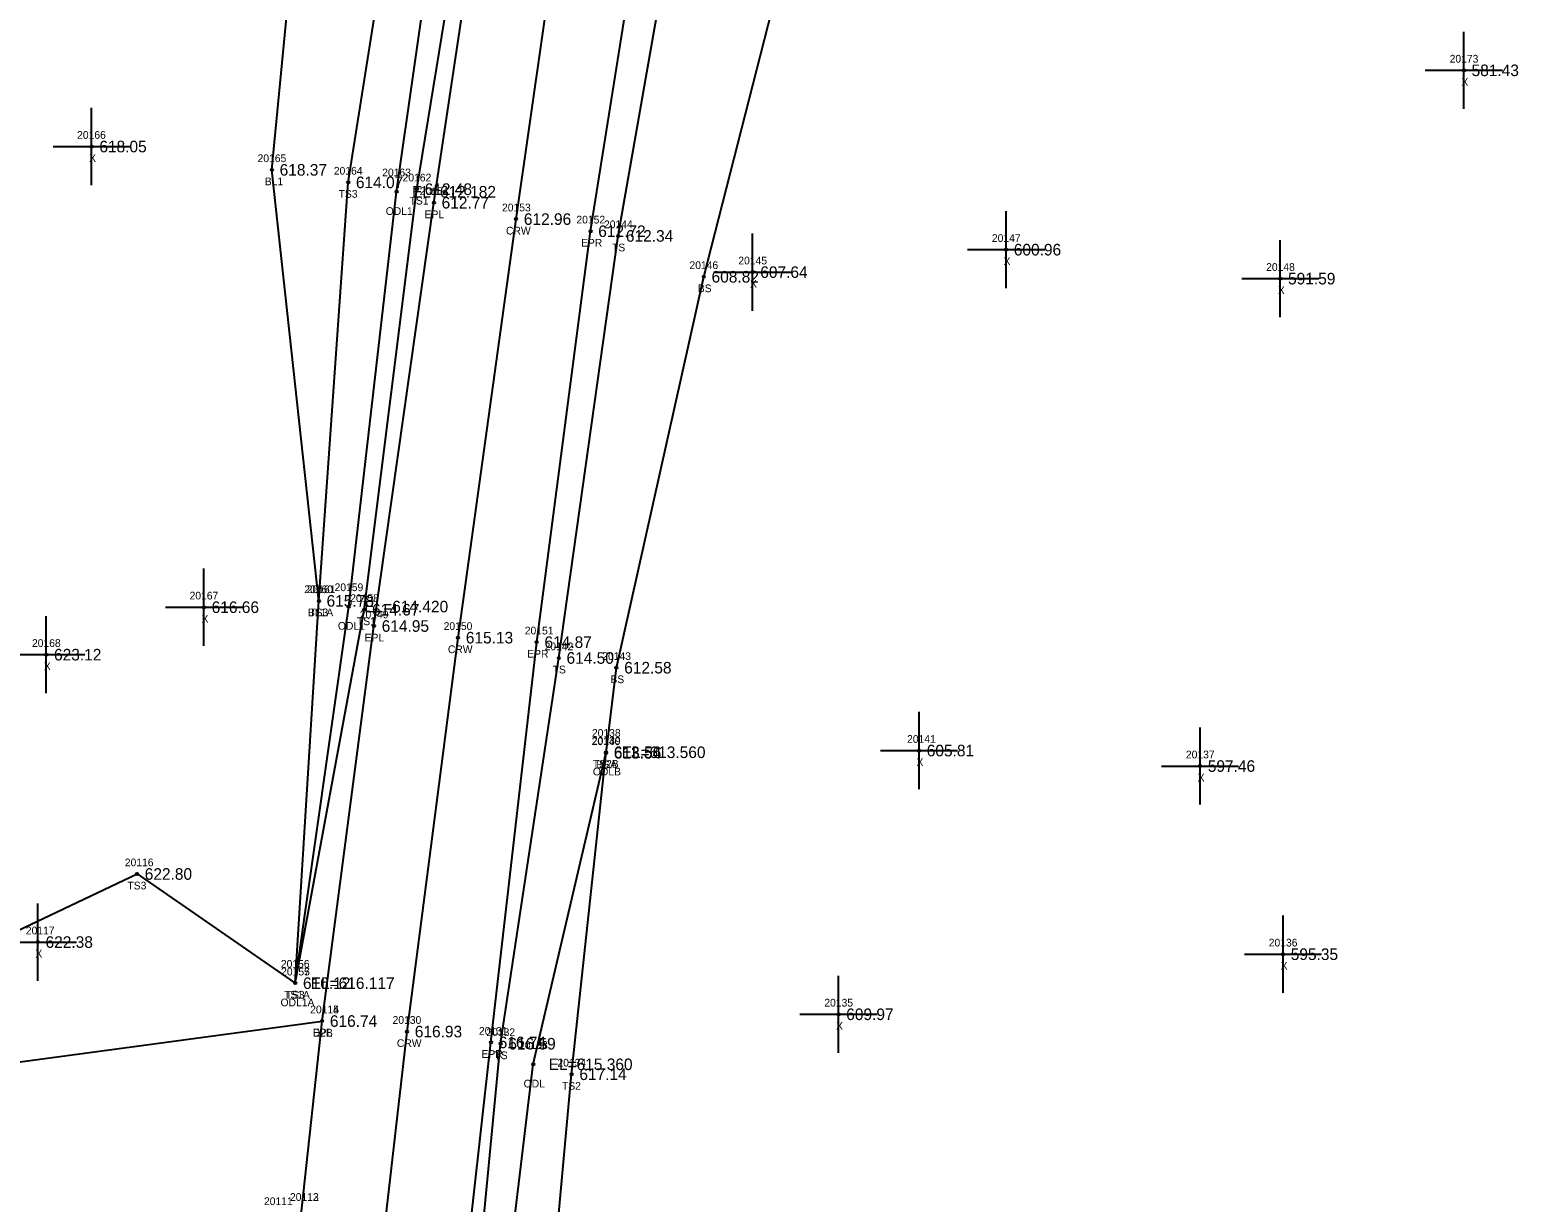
# Model space of a CAD drawing. Extents: x 1695443 to 1696344, y 1087542 to 1090645.
# Drawn here: x 1695882.4 to 1696075.2, y 1088055.6 to 1088207.5 of the extents above; entities that cross this region are included whole.
import ezdxf

# ---------------------------------------------------------------- set-up
doc = ezdxf.new("R2010")
doc.units = 0
for name, color, linetype in [('RD_DTM_BkLn1', 7, 'Continuous'), ('RD_DTM_BkLn2', 7, 'Continuous'), ('RD_DTM_BkLn_txCode', 7, 'Continuous'), ('RD_EX_Driveway', 7, 'Continuous'), ('RD_EX_Driveway_txCode', 7, 'Continuous'), ('RD_EX_H2O', 7, 'Continuous'), ('RD_EX_H2O_txCode', 7, 'Continuous'), ('RD_EX_Misc', 7, 'Continuous'), ('RD_EX_Misc_txCode', 7, 'Continuous'), ('RD_EX_Road', 7, 'Continuous'), ('RD_EX_Road_txCode', 7, 'Continuous'), ('RD_EX_TX_Driveway_ELEV', 7, 'Continuous'), ('RD_EX_TX_H2O_ELEV', 7, 'Continuous'), ('RD_EX_TX_Misc_ELEV', 7, 'Continuous'), ('RD_EX_TX_Road_ELEV', 7, 'Continuous'), ('RD_HC_Survey_ELEV', 7, 'Continuous'), ('RD_HC_Survey_txCode', 7, 'Continuous'), ('RD_SMD_Locator', 7, 'Continuous')]:
    doc.layers.add(name, color=color, linetype=linetype)

msp = doc.modelspace()

# ---------------------------------------------------------------- linework, layer by layer
at = {"layer": 'RD_DTM_BkLn1'}
for points in [[(1695869.23, 1087563.38), (1695882.71, 1087666.87), (1695895.39, 1087768.85), (1695908.05, 1087871.3), (1695919.71, 1087974.19), (1695925.35, 1088026.13), (1695931.27, 1088077.73), (1695937.88, 1088128.75), (1695945.4, 1088182.97), (1695952.48, 1088232.38), (1695961.74, 1088286.36), (1695971.36, 1088336.92), (1695982.91, 1088390.82), (1696009.16, 1088497.22), (1696035.45, 1088601.7), (1696045.5, 1088655.66), (1696049.03, 1088705.78), (1696045.47, 1088756.42), (1696033.82, 1088809.1), (1696016.78, 1088855.71), (1695990.89, 1088906.17), (1695964.41, 1088947.39), (1695931.21, 1088992.88)], [(1695919.84, 1088133.52), (1695913.76, 1088189.35), (1695918.21, 1088235.47), (1695922.76, 1088289.81), (1695929.86, 1088337.9), (1695944.4, 1088398.9), (1695974.86, 1088502.33), (1696013.19, 1088605.35)]]:
    msp.add_lwpolyline(points, dxfattribs=at)
at = {"layer": 'RD_DTM_BkLn2'}
for points in [[(1695957.06, 1088113.83), (1695958.4, 1088124.86), (1695969.72, 1088175.5), (1695984.45, 1088233.12), (1695986.34, 1088280.33), (1695995.02, 1088332.7), (1696009.2, 1088386.54), (1696038.3, 1088489.24), (1696061.78, 1088594.39), (1696062.98, 1088655.37), (1696069.05, 1088704.28), (1696065.26, 1088759.68), (1696052.53, 1088814.08), (1696046.96, 1088869.93), (1696016.66, 1088919.05), (1695997.75, 1088967.45), (1695944.59, 1089014.67), (1695937.23, 1089009.08)], [(1695916.78, 1088084), (1695925.73, 1088132.37), (1695932.55, 1088186.85), (1695940.12, 1088233.39), (1695949.48, 1088288.14), (1695959.7, 1088339.01), (1695971.73, 1088394.21), (1695997.36, 1088500.21), (1696023.08, 1088603.25), (1696032.92, 1088656.94), (1696036.1, 1088705.18), (1696032.76, 1088754.54), (1696021.34, 1088805.78), (1696004.42, 1088850.43), (1695979.2, 1088899.43), (1695947.85, 1088934.07), (1695935.29, 1088941.42), (1695930.1, 1088962.13), (1695923.44, 1088976.06), (1695917.46, 1088980.5), (1695920.03, 1088983.92)], [(1695811.33, 1088056.44), (1695848.8, 1088075.62), (1695896.28, 1088098.14), (1695916.78, 1088084), (1695919.84, 1088133.52), (1695923.64, 1088187.73), (1695930.8, 1088232.96), (1695939.58, 1088289.44), (1695949.3, 1088339.9), (1695960.86, 1088397.31), (1695988.69, 1088500.86), (1696013.19, 1088605.35), (1696020.87, 1088659.75), (1696023.4, 1088706.14), (1696018.3, 1088755.38), (1696009.58, 1088802.31), (1695993.24, 1088846.7), (1695969.88, 1088894.03), (1695962.8, 1088910.68)], [(1695882.6, 1087560.4), (1695895.55, 1087664.54), (1695908.06, 1087766.74), (1695920.67, 1087869.68), (1695933.47, 1087972.17), (1695938.06, 1088020.68), (1695943.39, 1088076.15), (1695950.93, 1088126.12), (1695958.62, 1088180.79), (1695967.59, 1088232.03), (1695975.32, 1088283.22), (1695985.14, 1088336.17), (1695996.59, 1088387.88), (1696023.18, 1088492.82), (1696049.23, 1088599.85), (1696058.32, 1088654.25)], [(1695882.6, 1087560.4), (1695883.79, 1087555.85), (1695890.5, 1087560.67), (1695906.06, 1087668.38), (1695920.19, 1087765.58), (1695932.4, 1087870.37), (1695944.02, 1087970.73), (1695947.56, 1088017.12), (1695952.59, 1088072.2), (1695957.06, 1088113.91)]]:
    msp.add_lwpolyline(points, dxfattribs=at)
at = {"layer": 'RD_EX_Driveway'}
msp.add_lwpolyline([(1695811.33, 1088056.44), (1695845.15, 1088068.97), (1695920.27, 1088079.09)], dxfattribs=at)
at = {"layer": 'RD_EX_H2O'}
for points in [[(1695916.78, 1088084), (1695923.72, 1088132.78), (1695929.91, 1088186.51), (1695936.75, 1088234.45), (1695946.8, 1088289.18), (1695957.47, 1088339.74), (1695969.14, 1088394.61), (1695994.85, 1088500.6), (1696021.07, 1088603.21), (1696031.1, 1088657.25), (1696033.92, 1088705.19), (1696029.81, 1088754.45), (1696018.23, 1088805.15), (1696001.4, 1088849.48), (1695973.58, 1088895.84), (1695962.8, 1088910.68)], [(1695884.7, 1087558.83), (1695897.39, 1087664.39), (1695910.4, 1087766.5), (1695924.17, 1087869.12), (1695936.94, 1087971.73), (1695941.17, 1088019.96), (1695947.61, 1088073.49), (1695957.06, 1088113.91)]]:
    msp.add_lwpolyline(points, dxfattribs=at)
at = {"layer": 'RD_EX_Misc'}
for p, q in [((1696068.19, 1088197.24), (1696068.19, 1088207.24)), ((1696063.19, 1088202.24), (1696073.19, 1088202.24)), ((1695890.4, 1088187.37), (1695890.4, 1088197.37)), ((1695885.4, 1088192.37), (1695895.4, 1088192.37)), ((1696008.88, 1088174.01), (1696008.88, 1088184.01)), ((1695976.03, 1088171.1), (1695976.03, 1088181.1)), ((1696044.41, 1088170.26), (1696044.41, 1088180.26)), ((1696003.88, 1088179.01), (1696013.88, 1088179.01)), ((1695971.03, 1088176.1), (1695981.03, 1088176.1)), ((1696039.41, 1088175.26), (1696049.41, 1088175.26)), ((1695904.95, 1088127.7), (1695904.95, 1088137.7)), ((1695884.53, 1088121.55), (1695884.53, 1088131.55)), ((1695899.95, 1088132.7), (1695909.95, 1088132.7)), ((1695879.53, 1088126.55), (1695889.53, 1088126.55)), ((1695997.6, 1088109.13), (1695997.6, 1088119.13)), ((1696034.01, 1088107.12), (1696034.01, 1088117.12)), ((1695992.6, 1088114.13), (1696002.6, 1088114.13)), ((1696029.01, 1088112.12), (1696039.01, 1088112.12)), ((1695883.43, 1088084.32), (1695883.43, 1088094.32)), ((1696044.76, 1088082.75), (1696044.76, 1088092.75)), ((1695878.43, 1088089.32), (1695888.43, 1088089.32)), ((1696039.76, 1088087.75), (1696049.76, 1088087.75)), ((1695987.17, 1088074.97), (1695987.17, 1088084.97)), ((1695982.17, 1088079.97), (1695992.17, 1088079.97))]:
    msp.add_line(p, q, dxfattribs=at)
at = {"layer": 'RD_EX_Road'}
for points in [[(1695879.87, 1087561.29), (1695893.33, 1087665.71), (1695905.96, 1087767.16), (1695918.66, 1087869.54), (1695930.87, 1087972.82), (1695936.26, 1088023.68), (1695942.14, 1088076.32), (1695948.07, 1088128.17), (1695955.04, 1088181.4), (1695962.88, 1088230.72), (1695971.68, 1088284.64), (1695982.02, 1088336.12), (1695993.28, 1088388.48), (1696018.75, 1088494.48), (1696045.23, 1088599.95), (1696055.72, 1088654.41), (1696060.15, 1088705.35), (1696055.83, 1088758.02), (1696044.01, 1088812.16), (1696026.4, 1088860.33), (1696000.41, 1088911.48), (1695972.46, 1088953.82), (1695939.48, 1088998.73), (1695931.21, 1088992.88)], [(1695858.19, 1087564.9), (1695871.71, 1087668.82), (1695884.5, 1087774.69), (1695887.48, 1087794.2), (1695897.57, 1087873.43), (1695908.92, 1087975.76), (1695914.49, 1088029.24), (1695917.65, 1088054.8), (1695920.27, 1088079.09), (1695926.98, 1088130.26), (1695934.75, 1088185.09), (1695942.15, 1088234.62), (1695951.36, 1088288.06), (1695961.48, 1088338.41), (1695972.86, 1088394.13), (1695998.53, 1088499.67), (1696024.81, 1088603.86), (1696034.83, 1088656.78)]]:
    msp.add_lwpolyline(points, dxfattribs=at)
at = {"layer": 'RD_SMD_Locator'}
for centre in [(1696068.19, 1088202.24), (1695890.4, 1088192.37), (1695913.76, 1088189.35), (1695923.64, 1088187.73), (1695929.91, 1088186.51), (1695932.55, 1088186.85), (1695934.75, 1088185.09), (1695945.4, 1088182.97), (1695955.04, 1088181.4), (1695958.62, 1088180.79), (1696008.88, 1088179.01), (1695969.72, 1088175.5), (1695976.03, 1088176.1), (1696044.41, 1088175.26), (1695919.84, 1088133.52), (1695919.84, 1088133.52), (1695904.95, 1088132.7), (1695923.72, 1088132.78), (1695925.73, 1088132.37), (1695926.98, 1088130.26), (1695937.88, 1088128.75), (1695948.07, 1088128.17), (1695884.53, 1088126.55), (1695950.93, 1088126.12), (1695958.4, 1088124.86), (1695957.06, 1088113.91), (1695957.06, 1088113.91), (1695957.06, 1088113.83), (1695997.6, 1088114.13), (1696034.01, 1088112.12), (1695896.28, 1088098.14), (1695883.43, 1088089.32), (1696044.76, 1088087.75), (1695916.78, 1088084), (1695916.78, 1088084), (1695916.78, 1088084), (1695920.27, 1088079.09), (1695920.27, 1088079.09), (1695987.17, 1088079.97), (1695931.27, 1088077.73), (1695942.14, 1088076.32), (1695943.39, 1088076.15), (1695947.61, 1088073.49), (1695952.59, 1088072.2)]:
    msp.add_circle(centre, 0.15, dxfattribs=at)

# ---------------------------------------------------------------- texts
at = {"layer": 'RD_DTM_BkLn_txCode'}
for s, p in [('20165', (1695911.9, 1088190.35)), ('20164', (1695921.78, 1088188.73)), ('BL1', (1695912.84, 1088187.35)), ('20162', (1695930.69, 1088187.85)), ('TS3', (1695922.4, 1088185.73)), ('TS1', (1695931.59, 1088184.85)), ('20144', (1695956.78, 1088181.79)), ('TS', (1695957.82, 1088178.79)), ('20146', (1695967.86, 1088176.5)), ('BS', (1695968.94, 1088173.5)), ('20160', (1695917.95, 1088134.52)), ('20161', (1695918.27, 1088134.52)), ('20158', (1695923.9, 1088133.37)), ('BL1A', (1695918.43, 1088131.52)), ('TS3', (1695918.6, 1088131.52)), ('TS1', (1695924.77, 1088130.37)), ('20142', (1695949.09, 1088127.12)), ('20143', (1695956.56, 1088125.86)), ('TS', (1695950.13, 1088124.12)), ('BS', (1695957.62, 1088122.86)), ('20140', (1695955.18, 1088114.83)), ('20139', (1695955.22, 1088114.91)), ('TS2B', (1695955.34, 1088111.91)), ('BSA', (1695955.79, 1088111.83)), ('20116', (1695894.7, 1088099.14)), ('TS3', (1695895.04, 1088096.14)), ('20155', (1695914.95, 1088085)), ('20157', (1695914.95, 1088085)), ('TS1A', (1695915.33, 1088082)), ('TS3', (1695915.54, 1088082)), ('20132', (1695941.55, 1088077.15)), ('TS', (1695942.59, 1088074.15)), ('20134', (1695950.75, 1088073.2)), ('TS2', (1695951.34, 1088070.2))]:
    msp.add_text(s, height=1, dxfattribs=at).set_placement(p)
at = {"layer": 'RD_EX_Driveway_txCode'}
for s, p in [('20115', (1695918.72, 1088080.09)), ('D2B', (1695919.05, 1088077.09)), ('20112', (1695916.1, 1088055.8))]:
    msp.add_text(s, height=1, dxfattribs=at).set_placement(p)
at = {"layer": 'RD_EX_H2O_txCode'}
for s, p in [('20163', (1695928.05, 1088188.51)), ('ODL1', (1695928.5, 1088183.51)), ('20159', (1695921.88, 1088134.78)), ('ODL1', (1695922.31, 1088129.78)), ('20138', (1695955.22, 1088115.91)), ('ODLB', (1695955.34, 1088110.91)), ('20156', (1695914.92, 1088086)), ('ODL1A', (1695914.88, 1088081)), ('20133', (1695945.78, 1088075.49)), ('ODL', (1695946.37, 1088070.49)), ('20111', (1695912.73, 1088055.25))]:
    msp.add_text(s, height=1, dxfattribs=at).set_placement(p)
at = {"layer": 'RD_EX_Misc_txCode'}
for s, p in [('20173', (1696066.35, 1088203.24)), ('X', (1696067.87, 1088200.24)), ('20166', (1695888.52, 1088193.37)), ('X', (1695890.08, 1088190.37)), ('20147', (1696007.04, 1088180.01)), ('20145', (1695974.19, 1088177.1)), ('X', (1696008.56, 1088177.01)), ('20148', (1696042.57, 1088176.26)), ('X', (1695975.71, 1088174.1)), ('X', (1696044.09, 1088173.26)), ('20167', (1695903.09, 1088133.7)), ('X', (1695904.64, 1088130.7)), ('20168', (1695882.67, 1088127.55)), ('X', (1695884.21, 1088124.55)), ('20141', (1695996.05, 1088115.13)), ('20137', (1696032.18, 1088113.12)), ('X', (1695997.28, 1088112.13)), ('X', (1696033.7, 1088110.12)), ('20117', (1695881.87, 1088090.32)), ('20136', (1696042.91, 1088088.75)), ('X', (1695883.11, 1088087.32)), ('X', (1696044.45, 1088085.75)), ('20135', (1695985.33, 1088080.97)), ('X', (1695986.85, 1088077.97))]:
    msp.add_text(s, height=1, dxfattribs=at).set_placement(p)
at = {"layer": 'RD_EX_Road_txCode'}
for s, p in [('20154', (1695932.91, 1088186.09)), ('EPL', (1695933.54, 1088183.09)), ('20152', (1695953.21, 1088182.4)), ('EPR', (1695953.81, 1088179.4)), ('20149', (1695925.14, 1088131.26)), ('EPL', (1695925.77, 1088128.26)), ('20151', (1695946.52, 1088129.17)), ('EPR', (1695946.84, 1088126.17)), ('20114', (1695918.72, 1088080.09)), ('EPL', (1695919.07, 1088077.09)), ('20131', (1695940.58, 1088077.32)), ('EPR', (1695940.91, 1088074.32)), ('20113', (1695916.1, 1088055.8))]:
    msp.add_text(s, height=1, dxfattribs=at).set_placement(p)
at = {"layer": 'RD_EX_TX_Driveway_ELEV'}
msp.add_text('616.74', height=1.5, dxfattribs=at).set_placement((1695921.27, 1088078.34))
at = {"layer": 'RD_EX_TX_H2O_ELEV'}
for s, p in [('EL=612.182', (1695931.91, 1088185.76)), ('EL=614.420', (1695925.72, 1088132.03)), ('EL=613.560', (1695959.06, 1088113.16)), ('EL=616.117', (1695918.78, 1088083.25)), ('EL=615.360', (1695949.61, 1088072.74))]:
    msp.add_text(s, height=1.5, dxfattribs=at).set_placement(p)
at = {"layer": 'RD_EX_TX_Misc_ELEV'}
for s, p in [('581.43', (1696069.19, 1088201.49)), ('618.05', (1695891.4, 1088191.62)), ('618.37', (1695914.76, 1088188.6)), ('614.07', (1695924.64, 1088186.98)), ('612.48', (1695933.55, 1088186.1)), ('612.34', (1695959.62, 1088180.04)), ('600.96', (1696009.88, 1088178.26)), ('608.82', (1695970.72, 1088174.75)), ('607.64', (1695977.03, 1088175.35)), ('591.59', (1696045.41, 1088174.51)), ('616.66', (1695905.95, 1088131.95)), ('615.78', (1695920.84, 1088132.77)), ('615.78', (1695920.84, 1088132.77)), ('614.67', (1695926.73, 1088131.62)), ('623.12', (1695885.53, 1088125.8)), ('614.50', (1695951.93, 1088125.37)), ('612.58', (1695959.4, 1088124.11)), ('613.56', (1695958.06, 1088113.16)), ('613.54', (1695958.06, 1088113.08)), ('605.81', (1695998.6, 1088113.38)), ('597.46', (1696035.01, 1088111.37)), ('622.80', (1695897.28, 1088097.39)), ('622.38', (1695884.43, 1088088.57)), ('595.35', (1696045.76, 1088087)), ('616.12', (1695917.78, 1088083.25)), ('616.12', (1695917.78, 1088083.25)), ('609.97', (1695988.17, 1088079.22)), ('616.59', (1695944.39, 1088075.4)), ('617.14', (1695953.59, 1088071.45))]:
    msp.add_text(s, height=1.5, dxfattribs=at).set_placement(p)
at = {"layer": 'RD_EX_TX_Road_ELEV'}
for s, p in [('612.77', (1695935.75, 1088184.34)), ('612.72', (1695956.04, 1088180.65)), ('614.95', (1695927.98, 1088129.51)), ('614.87', (1695949.07, 1088127.42)), ('616.74', (1695921.27, 1088078.34)), ('616.74', (1695943.14, 1088075.57))]:
    msp.add_text(s, height=1.5, dxfattribs=at).set_placement(p)
at = {"layer": 'RD_HC_Survey_ELEV'}
for s, p in [('612.96', (1695946.4, 1088182.22)), ('615.13', (1695938.88, 1088128)), ('616.93', (1695932.27, 1088076.98))]:
    msp.add_text(s, height=1.5, dxfattribs=at).set_placement(p)
at = {"layer": 'RD_HC_Survey_txCode'}
for s, p in [('20153', (1695943.57, 1088183.97)), ('CRW', (1695944.09, 1088180.97)), ('20150', (1695936.01, 1088129.75)), ('CRW', (1695936.56, 1088126.75)), ('20130', (1695929.39, 1088078.73)), ('CRW', (1695929.95, 1088075.73))]:
    msp.add_text(s, height=1, dxfattribs=at).set_placement(p)

doc.saveas('drawing.dxf')
